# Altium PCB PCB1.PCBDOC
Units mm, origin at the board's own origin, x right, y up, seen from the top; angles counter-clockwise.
Board outline 152.4 x 101.6 mm, 2 copper layers (Top Layer, Bottom Layer); 41 components, 23 nets, 101 pads, 2 vias.
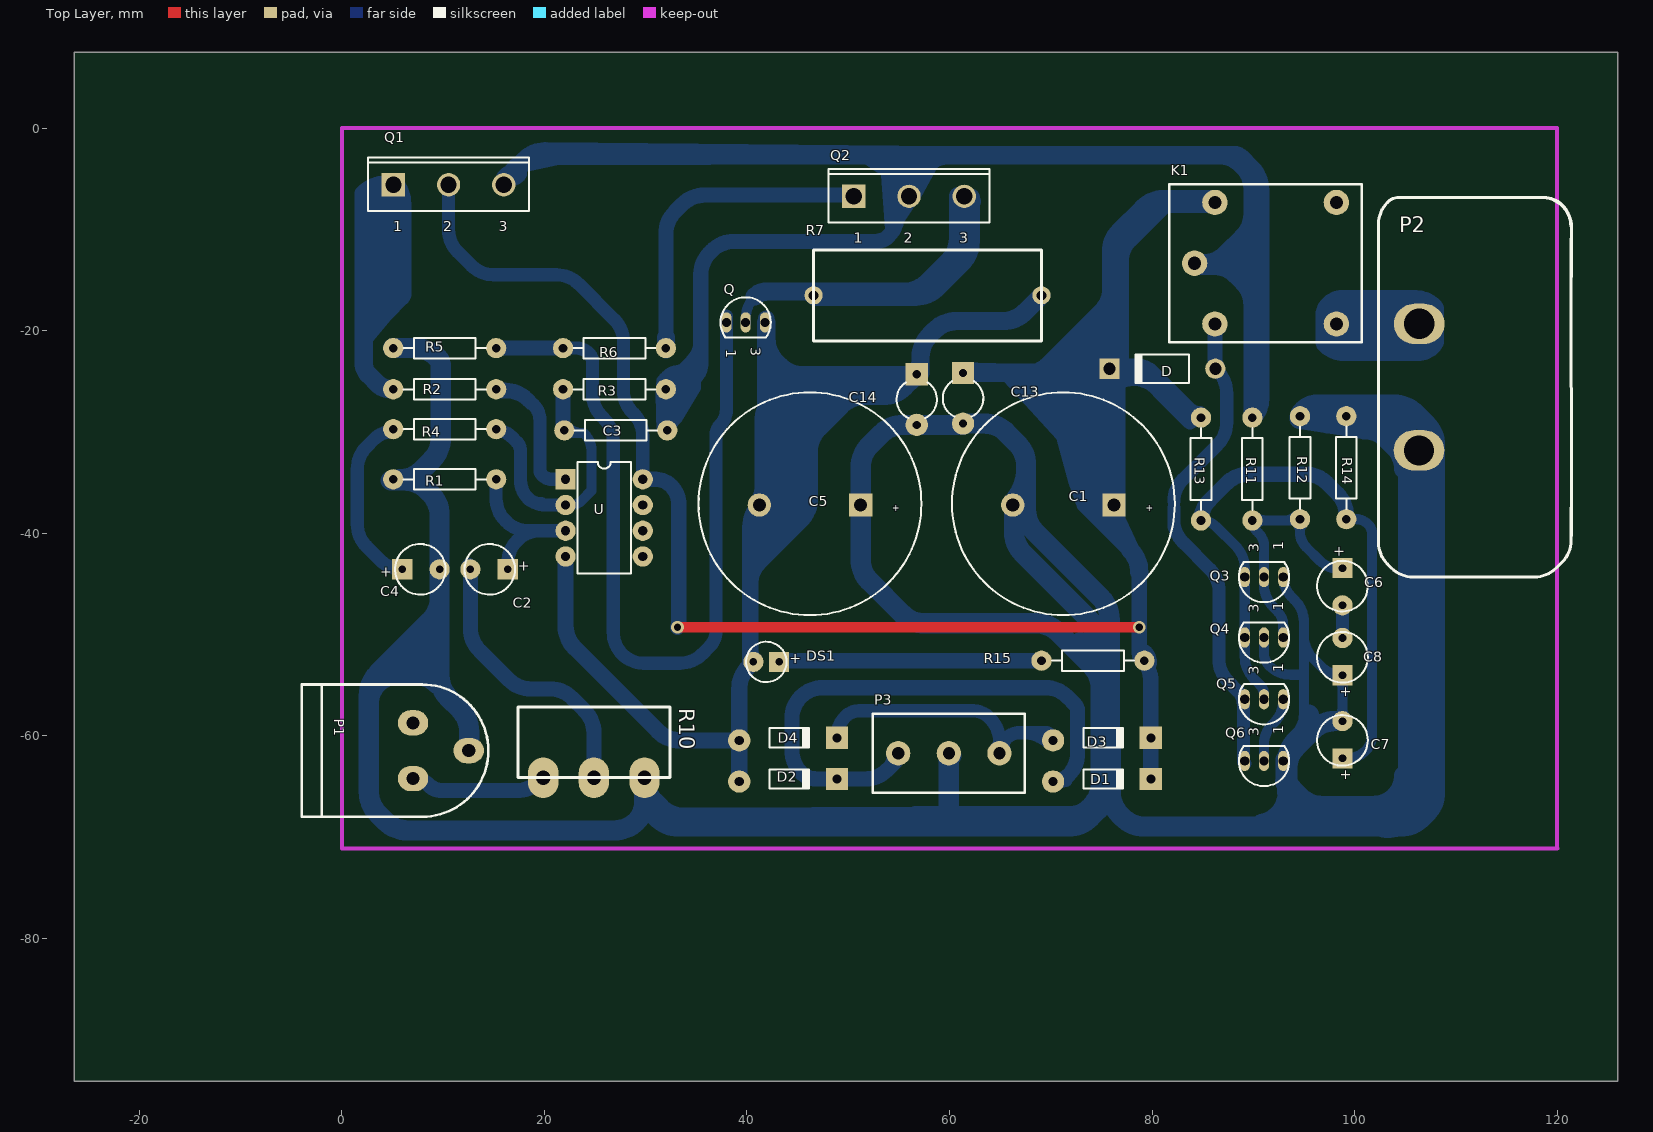
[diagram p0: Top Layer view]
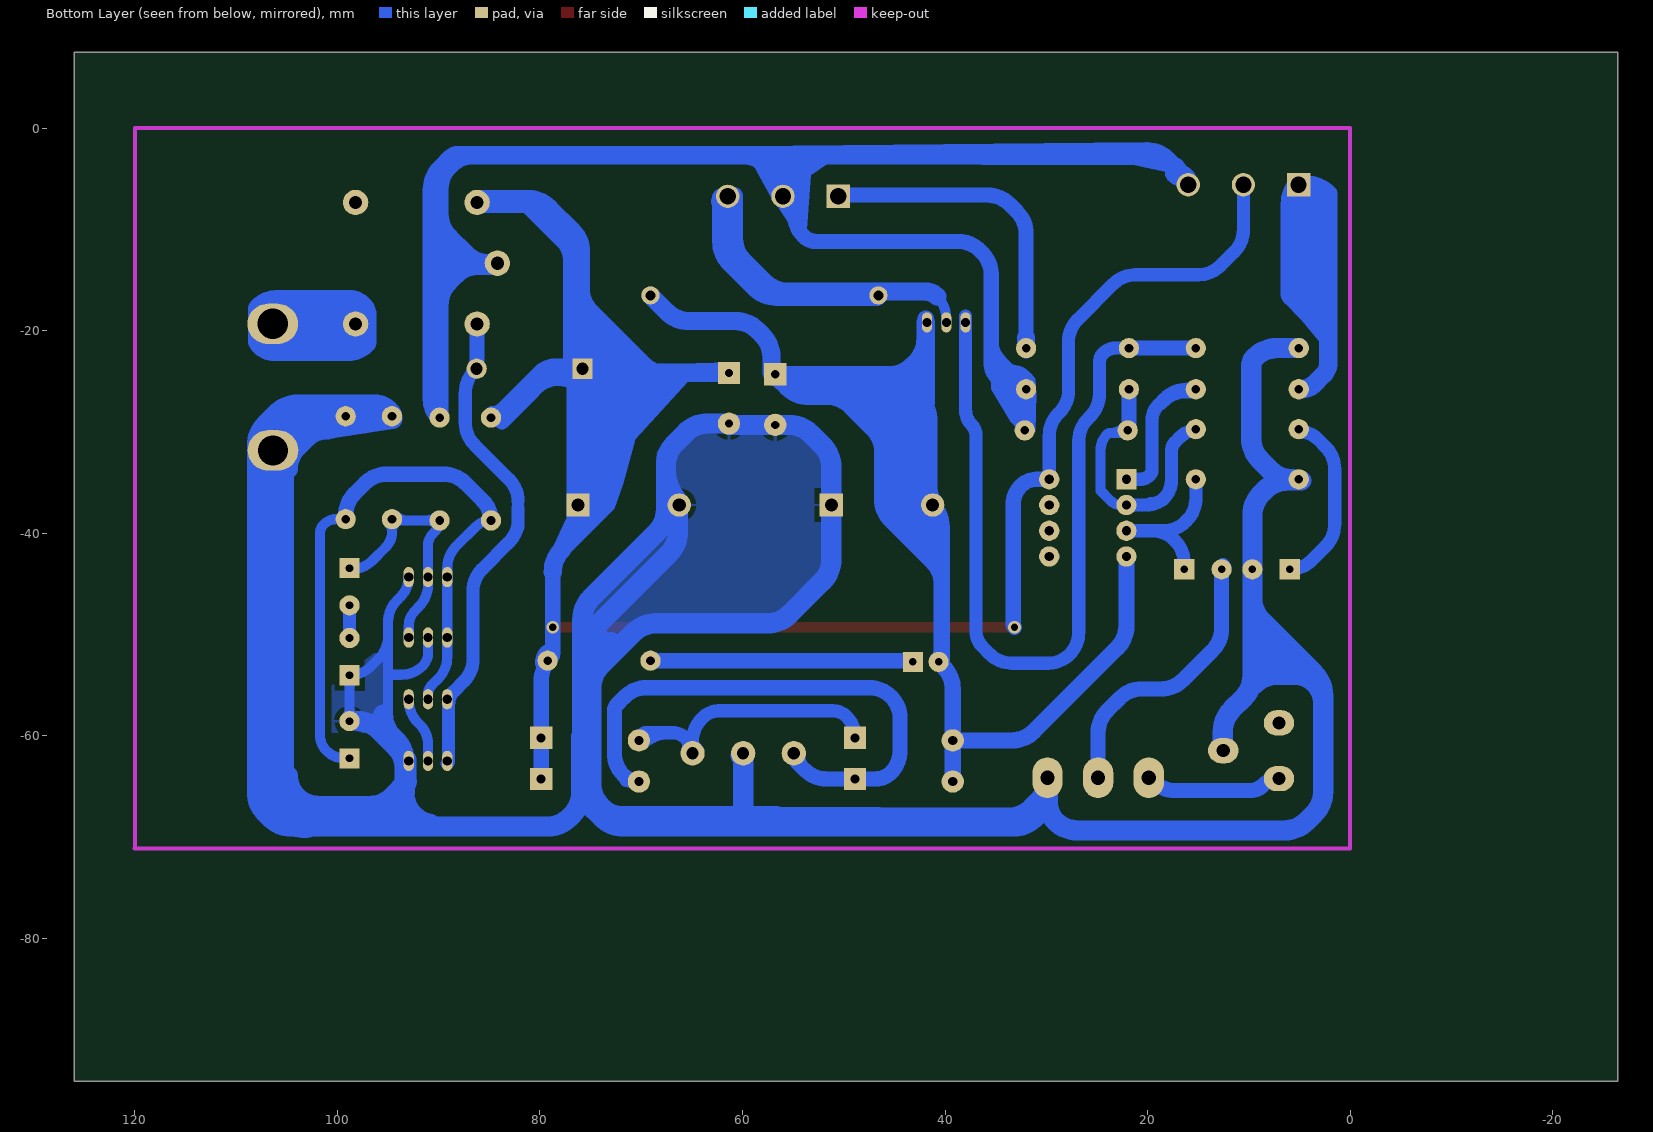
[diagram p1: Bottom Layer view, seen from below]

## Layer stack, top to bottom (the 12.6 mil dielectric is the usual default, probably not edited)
Top Layer: signal copper 0.0356
Dielectric: dielectric 0.32, FR-4, Dk 4.8
Bottom Layer: signal copper 0.0356

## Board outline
-26.416,-94.107 125.984,-94.107 125.984,7.493 -26.416,7.493

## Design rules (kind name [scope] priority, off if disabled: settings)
Clearance [All] p1: gap=0.5
ComponentClearance [All] p1: gap=0.254 collisioncheckmode=3
PolygonConnect [All] p1: connectstyle=Relief reliefconductorwidth=0.254 reliefentries=4 polygonreliefangle="90 Angle"
RoutingVias [All] p1: holewidth=0.711 width=1.27 viastyle="Through Hole" minholewidth=0.711 minwidth=1.27 maxholewidth=0.711 maxwidth=1.27
SolderMaskExpansion [All] p1: expansion=0.102
TestPointUsage [All] p1: valid=0 allowmultiple=FALSE
Testpoint [All] p1: side=3 testpointundercomponent=TRUE minsize=1.016 maxsize=2.54 preferedsize=1.524 minholesize=0 maxholesize=1.016 preferedholesize=0.813 testpointgrid=0.025 style=297 order=1234567890
Width Width_3 [InNet('GND')] p1: maxlimit=2.5 minlimit=0.8 preferedwidth=1.5 bottomlayer_prefwidth=2 minimp=50.000000 maximp=50.000000 favimp=50.000000
Width Width_2 [InNet('-12V')] p2: maxlimit=1.8 minlimit=0.5 preferedwidth=1 bottomlayer_prefwidth=1.6 minimp=50.000000 maximp=50.000000 favimp=50.000000
Width Width_1 [InNet('+12V')] p3: maxlimit=1.8 minlimit=0.5 preferedwidth=1 bottomlayer_prefwidth=1.5 minimp=50.000000 maximp=50.000000 favimp=50.000000
Width [All] p4: maxlimit=3 minlimit=0.4 preferedwidth=1 bottomlayer_prefwidth=1.5 minimp=50.000000 maximp=50.000000 favimp=50.000000
17 further rules are at their usual default settings.

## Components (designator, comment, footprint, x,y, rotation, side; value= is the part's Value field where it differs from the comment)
C1 "Cap Pol1" RB7.6-15 71.247,-37.084 r0 top
C2 "Cap Pol1" CAPPR2-5x6.8 14.605,-43.561 r180 top
C3 "Cap" AXIAL-0.4 27.051,-29.845 r0 top
C4 "Cap Pol1" CAPPR2-5x6.8 7.747,-43.561 r0 top
C5 "Cap Pol1" RB7.6-15 46.228,-37.084 r0 top
C6 "Cap Pol1" CAPPR2-5x6.8 98.806,-45.212 r270 top
C7 "Cap Pol1" CAPPR2-5x6.8 98.806,-52.248 r90 top
C8 "Cap Pol1" CAPPR2-5x6.8 98.806,-60.452 r90 top
C13 "Cap" CAPR5-4X5 61.341,-26.67 r270 top
C14 "Cap" CAPR5-4X5 56.769,-26.797 r270 top
D "1N4001" DIO10.46-5.3x2.8 81.026,-23.749 r180 top
D1 "Diode 1N914" DIO7.1-3.9x1.9 75.184,-64.262 r0 top
D2 "Diode 1N914" DIO7.1-3.9x1.9 44.196,-64.262 r0 top
D3 "Diode 1N914" DIO7.1-3.9x1.9 75.184,-60.198 r0 top
D4 "Diode 1N914" DIO7.1-3.9x1.9 44.196,-60.198 r0 top
DS1 "LED0" CAPPR1.5-4x5 41.91,-52.705 r180 top
K1 "Relay-SPDT" jidianqi 84.201,-13.335 r0 top
P1 "Header 2" 音频线 9.779,-61.468 r270 top
P2 "Header 2" pcZOU 102.362,-44.323 r90 top
P3 "Header 3" duanzi 59.944,-61.722 r180 top
Q "BC547" BCY-W3/E4 39.878,-19.177 r270 top
Q1 "IRFPC50" TO-247AC 10.541,-5.588 r0 top
Q2 "IRFPC50" TO-247AC 56.007,-6.731 r0 top
Q3 "9014" BCY-W3/E4 91.059,-44.323 r90 top
Q4 "9014" BCY-W3/E4 91.059,-50.292 r90 top
Q5 "8050" BCY-W3/E4 91.059,-56.388 r90 top
Q6 "8050" BCY-W3/E4 91.059,-62.484 r90 top
R1 "Res2" AXIAL-0.4 10.16,-34.671 r180 top
R2 "Res2" AXIAL-0.4 10.16,-25.781 r180 top
R3 "Res2" AXIAL-0.4 26.924,-25.781 r0 top
R4 "Res2" AXIAL-0.4 10.16,-29.718 r0 top
R5 "Res2" AXIAL-0.4 10.16,-21.717 r0 top
R6 "Res2" AXIAL-0.4 26.924,-21.717 r0 top
R7 "Res2" "0.02R   5W" 69.088,-16.51 r180 top
R10 "" 电位器 24.892,-64.135 r0 top
R11 "Res2" AXIAL-0.4 89.916,-33.655 r90 top
R12 "Res2" AXIAL-0.4 94.615,-33.528 r90 top
R13 "Res2" AXIAL-0.4 84.836,-33.655 r270 top
R14 "Res2" AXIAL-0.4 99.187,-33.528 r90 top
R15 "Res2" AXIAL-0.4 74.168,-52.578 r0 top
U "NE5532AP" P008 25.908,-38.481 r270 top

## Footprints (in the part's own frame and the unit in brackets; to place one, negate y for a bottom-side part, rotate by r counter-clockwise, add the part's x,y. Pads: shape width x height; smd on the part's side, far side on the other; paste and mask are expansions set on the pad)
"0.02R   5W" [mm]
  round 1.8 hole 1: 1(0,0) 2(22.5,0)
  silkscreen extent 0,-4.5 22.5,4.5
AXIAL-0.4 [mm] "Connector; Header; 2 Posi"
  round 2 hole 0.85: 1(-5.08,0) 2(5.08,0)
  silkscreen extent -4.06,-1.02 4.06,1.02
BCY-W3/E4 [mm]
  oval 2x1 hole 0.9: 1(0,-1.905) 2(0,0) 3(0,1.905)
  silkscreen extent -2.48,-2.48 1.5,2.48
CAPPR1.5-4x5 [mm]
  rect 2x2 hole 0.75: 1(-1.27,0)
  round 2 hole 0.75: 2(1.27,0)
  silkscreen extent -2,-2 2,2
CAPPR2-5x6.8 [mm] "Connector; Header; 2 Posi"
  rect 2x2 hole 0.75: 1(-1.778,0)
  round 2 hole 0.75: 2(1.905,0)
  silkscreen extent -2.5,-2.5 2.5,2.5
CAPR5-4X5 [mm] "Connector; Header; 2 Posi"
  rect 2.2x2.2 hole 0.8: 1(-2.5,0)
  round 2.2 hole 0.8: 2(2.5,0)
  silkscreen extent -1.69,-2 1.82,2
DIO7.1-3.9x1.9 [mm] "Connector; Header; 2 Posi"
  round 2.2 hole 0.9: 1(-4.953,-0.254)
  rect 2.2x2.2 hole 0.9: 2(4.699,0)
  silkscreen extent -1.95,-0.95 2.05,0.95
DIO10.46-5.3x2.8 [mm] "Connector; Header; 2 Posi"
  round 2 hole 1.2: 1(-5.23,0)
  rect 2x2 hole 1.2: 2(5.23,0)
  silkscreen extent -2.65,-1.4 2.75,1.4
duanzi [mm]
  round 2.4 hole 1.2: 1(-4.994,0) 2(0.006,0) 3(5.006,0)
  silkscreen extent -7.49,-3.9 7.51,3.9
jidianqi [mm]
  round 2.5 hole 1.3: 1(14.006,-6) 2(14.006,6) 3(0.006,0) 4(2.006,-6) 5(2.006,6)
  silkscreen extent -2.49,-7.8 16.51,7.8
P008 [mm]
  rect 2x2 hole 0.9: 1(-3.81,-3.81)
  round 2 hole 0.9: 2(-1.27,-3.81) 3(1.27,-3.81) 4(3.81,-3.81) 5(3.81,3.81) 6(1.27,3.81) 7(-1.27,3.81) 8(-3.81,3.81)
  silkscreen extent -5.5,-2.65 5.5,2.65
pcZOU [mm]
  oval 4x5 hole 3: 1(25,-4.025) 2(12.5,-4)
  silkscreen extent 0,-19.08 37.5,0
RB7.6-15 [mm]
  rect 2.3x2.3 hole 1.3: 1(5,-0.127)
  round 2.3 hole 1.3: 2(-5,-0.127)
  silkscreen extent -11,-11 11,11
TO-247AC [mm]
  rect 2.3x2.3 hole 1.6: 1(-5.45,0)
  round 2.3 hole 1.6: 2(0,0) 3(5.45,0)
  silkscreen extent -7.95,-2.6 7.95,2.7
电位器 [mm]
  oval 3x4 hole 1.4: 1(-5,0) 2(0,0) 3(5,0)
  silkscreen extent -7.51,0 7.5,6.98
音频线 [mm]
  oval 2.5x3 hole 1.3: 1(-0.007,2.75) 2(2.75,-2.75) 3(-2.75,-2.75)
  silkscreen extent -6.54,-13.75 6.52,4.69

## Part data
C1: "Polarized Capacitor (or (tor (ed Capacitor ( 2-Pin"
C2 C4: "Polarized Capacitor (tor (ed Capacitor ( 2-Pin"
C3: "CapacCapacitor (tor (ed Capacitor ( 2-Pin"
C5: "Polarized Capacitor (pacitor (ed Capacitor ( 2-Pin"
C6 C7: "Polarized Capacitor (ed Capacitor ( 2-Pin"
C8: "Polarized Capacitor ( 2-Pin"
C13 C14: "Cauctance Fasose Re=Header, 2-Pin"
D: library part "Diode 1N4001", "1 Amp General Purpose Re=Header, 2-Pin"
D1 D2 D3 D4: "High Conductance Fasose Re=Header, 2-Pin"
DS1: "Typical INFRARED G"
K1: "Single-Pole Dual-Throw"
P1 P2: "Header, 2-Pin"
P3: "HeaderFET Powere AmSOURCEDESCRIPTION=Single-Pole Dual-Throw"
Q: library part 2N3904, "NPN General Purpose AmSOURCEDESCRIPTION=Single-Pole Dual-Throw"
Q1 Q2: "HEXFET Powere AmSOURCEDESCRIPTION=Single-Pole Dual-Throw"
Q3: library part 2N3904, "NPN General Purpose AmERENCE=Relay-SPDT"
Q4 Q5 Q6: library part 2N3904, "NPN General Purpose AmGeneral Purpose AmSOURCEDESCRIPTION=Single-Pole Dual-Throw"
R1 R2 R3 R4 R5 R6: "RSOURCEDESCRIPTION=RRtional Am INFRARED G"
R7: "RRtional Am INFRARED G"
R10: library part RPot, "Potentiometer"
R11 R12 R13 R14: "RSOURCEDESCRIPTION=Rtional Am INFRARED G"
R15: "Rtional Am INFRARED G"
U: "Dual Low-Noise Operational Am INFRARED G"

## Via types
v1: diameter 1.27, hole 0.711, Top Layer to Bottom Layer, 2 vias

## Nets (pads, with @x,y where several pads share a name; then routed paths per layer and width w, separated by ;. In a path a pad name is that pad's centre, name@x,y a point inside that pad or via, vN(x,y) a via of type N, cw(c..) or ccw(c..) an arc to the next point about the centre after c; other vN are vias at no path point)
+12V: C1.1 C13.1 D1.2 D3.2 D.2 K1.5 Q1.2 R13.1 R15.2 U.8 | length 252.5
  Top Layer w1: v1(33.147,-49.276) v1(78.74,-49.276)
  Bottom Layer w1.3: Q1.2 10.541,-10.033 ccw(c13.607,-10.033) 11.439,-12.201 12.818,-13.58 ccw(c14.986,-11.412) 14.986,-14.478 21.209,-14.478 cw(c21.209,-17.544) 23.377,-15.376 26.915,-18.914 cw(c24.747,-21.082) 27.813,-21.082 27.813,-25.908 ccw(c30.879,-25.908) 28.711,-28.076 28.82,-28.185 cw(c26.652,-30.353) 29.718,-30.353 U.8
  Bottom Layer w1.5: U.8 30.979,-34.671 cw(c30.979,-36.839) 32.512,-35.306 cw(c30.672,-37.146) 33.274,-37.146 33.274,-48.969 cw(c32.84,-48.969) v1(33.147,-49.276) ; C13.1 67.524,-24.17 ccw(c67.524,-21.104) 69.692,-23.272 74.921,-18.043 ccw(c72.753,-15.875) 75.796,-16.25 ccw(c72.753,-15.875) 75.819,-15.875 ; C1.1@75.796,-36.122 75.796,-25.123 ; D.2@75.796,-23.495 78.477,-23.495 cw(c78.477,-25.663) 80.01,-24.13 83.625,-27.745 ccw(c84.709,-26.661) R13.1@84.709,-28.194 ; 75.796,-15.875 75.796,-12.215 cw(c78.862,-12.215) 76.694,-10.047 78.985,-7.756 cw(c81.153,-9.924) 81.153,-6.858 K1.5@85.725,-6.858 ; 76.581,-25.146 cw(c78.181,-27.762) 80.349,-25.594 ; 76.581,-12.192 cw(c79.34,-12.192) 77.389,-10.241 ; 76.754,-11.13 80.01,-7.874 ; 76.962,-23.876 76.962,-13.081 cw(c79.721,-13.081) 77.77,-11.13 81.026,-7.874 cw(c81.639,-8.487) 81.639,-7.62 K1.5@86.106,-7.62 ; 78.74,-43.815 78.74,-51.838 ccw(c79.607,-51.838) 78.994,-52.451 cw(c76.848,-54.597) 79.883,-54.597 D1.2 ; R15.2@79.307,-51.748 cw(c78.223,-52.832) R15.2@79.756,-52.832 ; 80.645,-25.917 83.752,-29.024 cw(c84.836,-30.108) R13.1 ; 75.796,-35.156 ccw(c78.302,-35.156) C1.1@76.53,-36.928 ; 75.796,-35.156 ccw(c78.302,-35.156) C1.1@76.53,-36.928 ; 75.796,-35.156 ccw(c78.302,-35.156) C1.1@76.53,-36.928 ; D.2@75.973,-23.926 cw(c77.013,-24.966) 77.013,-23.495 ; D.2@75.973,-23.926 cw(c77.013,-24.966) 77.013,-23.495 ; D.2@75.973,-23.926 cw(c77.013,-24.966) 77.013,-23.495 ; 78.74,-50.748 ccw(c81.078,-50.748) R15.2@79.425,-52.401 ; 78.74,-50.748 ccw(c81.078,-50.748) R15.2@79.425,-52.401 ; 78.74,-50.748 ccw(c81.078,-50.748) R15.2@79.425,-52.401 ; 83.759,-27.879 ccw(c84.836,-26.802) R13.1@84.836,-28.325 ; 83.759,-27.879 ccw(c84.836,-26.802) R13.1@84.836,-28.325 ; 83.759,-27.879 ccw(c84.836,-26.802) R13.1@84.836,-28.325 ; 83.816,-27.936 ccw(c84.76,-26.991) R13.1@84.824,-28.325 ; 83.816,-27.936 ccw(c84.76,-26.991) R13.1@84.824,-28.325 ; 83.816,-27.936 ccw(c84.76,-26.991) R13.1@84.824,-28.325 ; 83.849,-6.858 cw(c83.849,-9.694) K1.5@85.854,-7.689 ; 83.849,-6.858 cw(c83.849,-9.694) K1.5@85.854,-7.689 ; 83.849,-6.858 cw(c83.849,-9.694) K1.5@85.854,-7.689
  Bottom Layer w1.8: 77.842,-41.647 cw(c75.674,-43.815) 78.74,-43.815
-12V: C5.2 C14.1 D2.1 D4.1 DS1.2 Q.3 R7.1 U.4 | length 187.1
  Bottom Layer w1.3: Q.3@41.783,-19.852 Q.3 ; C14.1 C14.1@57.277,-24.297
  Bottom Layer w1.6: U.4 22.098,-49.149 ccw(c25.164,-49.149) 22.996,-51.317 31.233,-59.554 ccw(c33.401,-57.386) 33.401,-60.452 D4.1 ; D2.1@39.116,-64.643 ccw(c38.809,-64.336) 39.243,-64.336 39.243,-55.372 cw(c42.309,-55.372) 40.141,-53.204 40.33,-53.015 40.33,-39.379 cw(c43.396,-39.379) C5.2 ccw(c40.501,-36.484) 41.402,-36.979 ccw(c40.501,-36.484) 41.529,-36.484 41.529,-28.956 cw(c44.595,-28.956) 42.427,-26.788 44.02,-25.195 cw(c46.188,-27.363) 46.188,-24.297 ; 40.33,-45.014 cw(c43.396,-45.014) 41.228,-42.846 45.33,-38.744 ccw(c43.162,-36.576) 46.228,-36.576 46.228,-31.877 cw(c49.294,-31.877) 47.126,-29.709 49.394,-27.441 cw(c51.562,-29.609) 51.562,-26.543 53.467,-26.543 ccw(c53.467,-23.477) 55.635,-25.645 56.462,-24.818 cw(c56.896,-25.251) C14.1@56.896,-24.638 ; C5.2@41.647,-37.347 ccw(c39.479,-35.179) 42.545,-35.179 42.545,-29.591 cw(c45.611,-29.591) 43.443,-27.423 45.33,-25.536 cw(c47.498,-27.704) 47.498,-24.638 C14.1@56.769,-24.638 ; 41.783,-27.095 Q.3 ; Q.3@42.037,-19.177 42.037,-20.828 ccw(c45.103,-20.828) 42.049,-21.102 ccw(c45.103,-20.828) 42.935,-22.996 43.338,-23.399 ccw(c45.506,-21.231) 45.506,-24.297 C14.1 ; 40.33,-51.474 ccw(c41.871,-51.474) DS1.2@40.781,-52.564 ; 40.33,-51.474 ccw(c41.871,-51.474) DS1.2@40.781,-52.564 ; 40.33,-51.474 ccw(c41.871,-51.474) DS1.2@40.781,-52.564 ; C5.2@40.981,-36.964 ccw(c39.656,-35.639) 41.529,-35.639 ; C5.2@40.981,-36.964 ccw(c39.656,-35.639) 41.529,-35.639 ; C5.2@40.981,-36.964 ccw(c39.656,-35.639) 41.529,-35.639 ; 55.221,-24.638 ccw(c55.221,-22.749) C14.1@56.557,-24.085 ; 55.221,-24.638 ccw(c55.221,-22.749) C14.1@56.557,-24.085 ; 55.221,-24.638 ccw(c55.221,-22.749) C14.1@56.557,-24.085
  Bottom Layer w1.8: C14.1@57.15,-24.17 57.15,-22.606 cw(c60.216,-22.606) 58.048,-20.438 58.538,-19.948 cw(c60.706,-22.116) 60.706,-19.05 65.278,-19.05 ccw(c65.278,-15.984) 67.446,-18.152 R7.1 ; C14.1@56.628,-24.156 ccw(c55.366,-22.894) 57.15,-22.894 ; C14.1@56.628,-24.156 ccw(c55.366,-22.894) 57.15,-22.894 ; C14.1@56.628,-24.156 ccw(c55.366,-22.894) 57.15,-22.894
GND: C1.2 C4.2 C5.1 C7.1 C8.2 C13.2 C14.2 P1.1 P2.2 P3.2 Q3.1 Q4.2 Q6.1 R1.2 R5.1 R10.3 R12.2 R14.2 | length 730.3
  Bottom Layer w1: Q4.2 91.059,-51.86 ccw(c92.793,-51.86) 91.567,-53.086 ccw(c93.713,-50.94) 93.713,-53.975 94.996,-53.975 ; Q3.1 ccw(c95.723,-44.323) 93.772,-46.274 94.098,-46.6 cw(c91.93,-48.768) 94.996,-48.768 94.996,-58.494 ccw(c95.43,-58.494) 95.123,-58.801 ; 94.996,-50.165 ccw(c98.062,-50.165) 95.894,-52.333 96.725,-53.164 ccw(c98.806,-51.082) C7.1@98.261,-53.975 ; C8.2@98.044,-58.547 C8.2 ; C7.1@98.683,-53.975 cw(c98.683,-54.148) C7.1 C8.2@98.806,-57.934 ; C4.2@9.298,-43.915 cw(c8.445,-44.768) 9.652,-44.768 ; C4.2@9.298,-43.915 cw(c8.445,-44.768) 9.652,-44.768 ; C4.2@9.298,-43.915 cw(c8.445,-44.768) 9.652,-44.768 ; 9.652,-44.768 cw(c10.859,-44.768) C4.2@10.006,-43.915 ; 9.652,-44.768 cw(c10.859,-44.768) C4.2@10.006,-43.915 ; 9.652,-44.768 cw(c10.859,-44.768) C4.2@10.006,-43.915 ; R12.2@94.969,-28.802 cw(c95.822,-29.655) 95.822,-28.448 ; R12.2@94.969,-28.802 cw(c95.822,-29.655) 95.822,-28.448 ; R12.2@94.969,-28.802 cw(c95.822,-29.655) 95.822,-28.448 ; R12.2@94.969,-28.094 ccw(c95.822,-27.241) 95.822,-28.448 ; R12.2@94.969,-28.094 ccw(c96.129,-26.934) 96.129,-28.575 ; R12.2@94.969,-28.094 ccw(c95.822,-27.241) 95.822,-28.448 ; R12.2@94.969,-28.094 ccw(c96.129,-26.934) 96.129,-28.575 ; R12.2@94.969,-28.094 ccw(c95.822,-27.241) 95.822,-28.448 ; R12.2@94.969,-28.094 ccw(c96.129,-26.934) 96.129,-28.575 ; 97.673,-28.575 ccw(c97.673,-26.934) R14.2@98.833,-28.094 ; 97.673,-28.575 ccw(c97.673,-26.934) R14.2@98.833,-28.094 ; 97.673,-28.575 ccw(c97.673,-26.934) R14.2@98.833,-28.094 ; 97.98,-28.448 cw(c97.98,-29.655) R14.2@98.833,-28.802 ; 97.98,-28.448 ccw(c97.98,-27.241) R14.2@98.833,-28.094 ; 97.98,-28.448 cw(c97.98,-29.655) R14.2@98.833,-28.802 ; 97.98,-28.448 ccw(c97.98,-27.241) R14.2@98.833,-28.094 ; 97.98,-28.448 cw(c97.98,-29.655) R14.2@98.833,-28.802 ; 97.98,-28.448 ccw(c97.98,-27.241) R14.2@98.833,-28.094 ; C8.2@98.452,-58.193 ccw(c97.599,-57.34) 98.806,-57.34 ; C8.2@98.452,-58.193 ccw(c97.599,-57.34) 98.806,-57.34 ; C8.2@98.452,-58.193 ccw(c97.599,-57.34) 98.806,-57.34 ; C7.1@98.452,-54.379 cw(c97.599,-55.233) 98.806,-55.233 ; C7.1@98.452,-54.379 cw(c97.599,-55.233) 98.806,-55.233 ; C7.1@98.452,-54.379 cw(c97.599,-55.233) 98.806,-55.233 ; 98.806,-57.34 ccw(c100.013,-57.34) C8.2@99.16,-58.193 ; 98.806,-57.34 ccw(c100.013,-57.34) C8.2@99.16,-58.193 ; 98.806,-57.34 ccw(c100.013,-57.34) C8.2@99.16,-58.193 ; 98.806,-55.233 cw(c100.013,-55.233) C7.1@99.16,-54.379 ; 98.806,-55.233 cw(c100.013,-55.233) C7.1@99.16,-54.379 ; 98.806,-55.233 cw(c100.013,-55.233) C7.1@99.16,-54.379 ; R12.2 ccw(c94.922,-28.141) 94.922,-28.575 99.314,-28.575 ccw(c99.007,-28.882) 99.007,-28.448 R12.2
  Bottom Layer w1.5: R14.2 101.981,-28.448 cw(c101.981,-31.514) 104.149,-29.346 P2.2@106.553,-31.75 ; 104.529,-28.329 cw(c102.357,-30.501) P2.2@105.39,-30.989 ; 103.767,-28.964 cw(c101.595,-31.136) P2.2@104.628,-31.624 ; 103.767,-28.964 cw(c101.595,-31.136) P2.2@104.628,-31.624 ; 103.767,-28.964 cw(c101.595,-31.136) P2.2@104.628,-31.624
  Bottom Layer w2: 2.667,-56.769 cw(c5.426,-56.769) 3.475,-54.818 cw(c5.51,-56.852) 5.51,-53.975 7.239,-53.975 cw(c7.239,-57.041) 9.407,-54.873 ; R1.2@4.826,-34.798 6.223,-34.798 cw(c6.223,-37.864) 7.798,-35.233 cw(c6.223,-37.864) 8.391,-35.696 8.754,-36.059 cw(c6.586,-38.227) 9.652,-38.227 9.652,-54.102 ccw(c12.718,-54.102) 10.55,-56.27 11.675,-57.395 cw(c9.507,-59.563) 12.573,-59.563 P1.1@12.573,-61.087 ; R5.1 7.239,-21.717 cw(c7.239,-24.783) 9.407,-22.615 cw(c8.509,-23.513) 9.779,-23.513 9.779,-30.607 cw(c6.713,-30.607) 8.881,-32.775 7.883,-33.773 cw(c5.715,-31.605) R1.2@5.715,-34.671 ; 5.461,-53.213 ccw(c5.461,-51.987) 6.328,-52.854 ; 5.588,-52.705 ccw(c5.588,-50.559) 7.106,-52.076 8.075,-51.107 cw(c8.509,-51.54) 8.509,-50.927 ; 6.604,-52.578 7.97,-52.578 cw(c7.97,-53.879) 8.89,-52.959 ; 9.652,-46.482 cw(c6.586,-46.482) 8.754,-48.65 3.565,-53.839 ccw(c5.733,-56.007) 2.667,-56.007 2.667,-65.532 ccw(c5.733,-65.532) 2.933,-66.78 ccw(c5.733,-65.532) 3.565,-67.7 4.309,-68.444 ccw(c6.477,-66.276) 6.477,-69.342 26.924,-69.342 ccw(c26.924,-66.276) 29.092,-68.444 ccw(c27.274,-66.626) 29.845,-66.656 ccw(c27.274,-66.626) 29.845,-66.626 R10.3@29.845,-63.754 ; R10.3 29.892,-64.309 ccw(c32.958,-64.309) 30.79,-66.477 31.487,-67.174 ccw(c33.655,-65.006) 33.655,-68.072 71.882,-67.945 ; R10.3@29.972,-64.389 29.972,-65.659 ccw(c33.038,-65.659) 30.87,-67.827 31.106,-68.063 ccw(c33.274,-65.895) 33.274,-68.961 71.755,-68.961 ccw(c71.755,-65.895) 73.923,-68.063 74.667,-67.319 ccw(c72.499,-65.151) 75.565,-65.151 ; 56.642,-67.945 ccw(c56.821,-64.884) 56.999,-67.945 71.882,-67.945 ; P3.2 59.938,-67.316 ccw(c60.827,-67.316) 60.198,-67.945 ; C13.2@61.341,-29.297 55.412,-29.297 ccw(c55.412,-32.363) 54.826,-29.354 ccw(c55.412,-32.363) 53.244,-30.195 52.126,-31.313 ccw(c54.294,-33.481) 51.228,-33.481 51.228,-42.592 ccw(c54.294,-42.592) 52.126,-44.76 55.363,-47.997 ccw(c57.531,-45.829) 57.531,-48.895 68.58,-48.895 cw(c68.58,-51.961) 70.748,-49.793 74.032,-53.077 cw(c71.864,-55.245) 74.93,-55.245 74.93,-64.77 cw(c71.864,-64.77) 74.032,-66.938 ; C13.2 63.46,-29.17 cw(c63.46,-32.236) 64.703,-29.433 cw(c63.46,-32.236) 65.628,-30.068 66.666,-31.106 cw(c64.498,-33.274) 67.564,-33.274 67.564,-37.719 ccw(c70.63,-37.719) 68.462,-39.887 74.921,-46.346 cw(c72.753,-48.514) 75.819,-48.514 75.819,-59.764 ccw(c76.253,-59.764) 75.946,-60.071 75.946,-65.659 ccw(c79.012,-65.659) 76.844,-67.827 77.08,-68.063 ccw(c79.248,-65.895) 79.248,-68.961 102.531,-68.961 ccw(c103.381,-66.015) 106.427,-65.671 106.43,-64.867 P2.2@106.553,-31.824 ; C1.2@66.374,-37.211 66.374,-39.831 ccw(c69.44,-39.831) 67.272,-41.999 75.048,-49.775 cw(c72.88,-51.943) 75.819,-51.07 ; 73.152,-51.562 ccw(c72.232,-51.562) 73.107,-51.277 ccw(c72.232,-51.562) 73.079,-51.203 cw(c75.964,-50.165) 72.949,-50.724 75.048,-52.823 cw(c72.88,-54.991) 75.819,-54.118 ; 73.833,-67.137 cw(c71.882,-65.186) 71.882,-67.945 ; 90.805,-68.707 ccw(c90.314,-65.681) 93.151,-64.52 ; 93.218,-64.643 Q6.1@93.218,-62.357 ; 93.345,-65.278 ccw(c96.411,-65.278) 94.243,-67.446 ; Q6.1@93.345,-63.246 cw(c96.411,-63.246) 94.243,-61.078 95.876,-59.445 cw(c98.044,-61.613) C8.2@98.044,-58.547 ; 93.726,-65.786 cw(c93.726,-67.012) 94.593,-66.145 95.114,-66.666 ccw(c97.282,-64.498) 97.282,-67.564 102.743,-67.564 ccw(c102.743,-64.498) 104.911,-66.666 ; 95.504,-57.912 cw(c92.438,-57.912) 94.606,-60.08 94.243,-60.443 ccw(c96.411,-62.611) 93.345,-62.611 93.345,-64.262 cw(c90.279,-64.262) 93.339,-64.454 ccw(c96.157,-63.246) 93.989,-65.414 94.606,-66.031 ccw(c96.774,-63.863) 96.774,-66.929 101.854,-66.929 ccw(c101.854,-63.863) 104.022,-66.031 ccw(c101.898,-63.907) 104.902,-63.907 ; 104.521,-68.961 ccw(c104.521,-65.895) 106.689,-68.063 107.052,-67.7 ccw(c104.884,-65.532) 107.95,-65.532 107.95,-31.369 ccw(c104.884,-31.369) 107.052,-29.201 106.054,-28.203 ccw(c103.886,-30.371) 103.886,-27.305 96.341,-27.305 ccw(c96.341,-29.326) 94.912,-27.897 ccw(c95.73,-28.715) 94.573,-28.715 99.035,-29.415 100.965,-29.718 cw(c100.965,-32.784) 103.133,-30.616 104.004,-31.487 cw(c101.836,-33.655) 104.902,-33.655 ; 105.283,-64.008 105.283,-33.756 ; C1.2@66.141,-37.105 ccw(c62.705,-33.669) 67.564,-33.669 ; C1.2@66.141,-37.105 ccw(c62.705,-33.669) 67.564,-33.669 ; C1.2@66.141,-37.105 ccw(c62.705,-33.669) 67.564,-33.669 ; 97.331,-29.148 ccw(c97.642,-27.163) R14.2 ; 97.331,-29.148 ccw(c97.642,-27.163) R14.2 ; 97.331,-29.148 ccw(c97.642,-27.163) R14.2 ; R14.2 ccw(c101.145,-27.577) 100.813,-29.694 ; R14.2 ccw(c101.145,-27.577) 100.813,-29.694 ; R14.2 ccw(c101.145,-27.577) 100.813,-29.694 ; 105.283,-35.635 cw(c109.674,-35.635) P2.2@106.569,-32.53 ; 105.283,-35.635 cw(c109.674,-35.635) P2.2@106.569,-32.53 ; 105.283,-35.635 cw(c109.674,-35.635) P2.2@106.569,-32.53 ; 105.283,-33.841 cw(c106.362,-33.841) P2.2@106.103,-32.794 ; 105.283,-33.841 cw(c106.362,-33.841) P2.2@106.103,-32.794 ; 105.283,-33.841 cw(c106.362,-33.841) P2.2@106.103,-32.794 ; P2.2@105.652,-32.527 cw(c103.476,-34.688) 106.542,-34.699 ; P2.2@105.652,-32.527 cw(c103.476,-34.688) 106.542,-34.699 ; P2.2@105.652,-32.527 cw(c103.476,-34.688) 106.542,-34.699
NetC2_1: C2.1 R1.1 U.3 | length 16.4
  Bottom Layer w1.3: R1.1 15.24,-36.576 ccw(c18.306,-36.576) 16.138,-38.744 16.247,-38.853 ccw(c18.415,-36.685) 18.415,-39.751 U.3 ; C2.1 16.383,-42.926 cw(c19.449,-42.926) 17.281,-40.758 17.39,-40.649 cw(c19.558,-42.817) 19.558,-39.751
  Bottom Layer w1.5: R1.1@15.367,-34.925 R1.1@15.367,-34.671
NetC2_2: C2.2 R10.2 | length 28.4
  Bottom Layer w1.5: C2.2@12.446,-43.561 12.446,-43.434 12.483,-43.397 ccw(c12.266,-43.18) C2.2@12.573,-43.18 ; C2.2 12.7,-49.403 ccw(c15.766,-49.403) 13.598,-51.571 16.501,-54.474 ccw(c18.669,-52.306) 18.669,-55.372 20.574,-55.372 cw(c20.574,-58.438) 22.742,-56.27 23.994,-57.522 cw(c21.826,-59.69) 24.892,-59.69 R10.2 ; R10.2@25.019,-64.389 R10.2@25.019,-64.135
NetC3_1: C3.1 R3.1 R4.2 U.2 | length 33
  Bottom Layer w1: C3.1@21.717,-30.099 23.696,-30.099 ; U.2 22.606,-37.211 ccw(c22.606,-35.678) 23.199,-37.092 ccw(c22.606,-35.678) 23.69,-36.762 24.638,-35.814 24.638,-31.759 ccw(c22.47,-31.759) 24.003,-30.226 ccw(c23.696,-30.533) 23.923,-30.163 ccw(c23.696,-30.533) 23.696,-30.099 ; C3.1@22.338,-29.505 ccw(c23.696,-28.248) 23.696,-30.099 ; C3.1@22.338,-29.505 ccw(c23.696,-28.248) 23.696,-30.099 ; C3.1@22.338,-29.505 ccw(c23.696,-28.248) 23.696,-30.099
  Bottom Layer w1.3: R4.2@15.24,-29.845 cw(c15.24,-31.991) 16.758,-30.474 17.272,-30.988 cw(c16.352,-31.908) 17.653,-31.908 17.653,-34.78 ccw(c20.149,-34.78) 18.384,-36.545 ccw(c19.685,-35.244) 19.138,-37.001 ; 19.685,-37.084 cw(c19.685,-35.244) 19.138,-37.001 ; R3.1@21.844,-26.035 R3.1 ; U.2 20.062,-37.211 cw(c20.062,-35.074) 19.138,-37.001
  Bottom Layer w1.5: C3.1@21.844,-29.845 R3.1@21.844,-25.527
NetC4_1: C4.1 R4.1 | length 17.7
  Bottom Layer w1.3: R4.1@4.953,-29.972 ccw(c4.953,-32.425) 3.219,-30.69 2.422,-31.487 ccw(c4.59,-33.655) 1.524,-33.655 1.524,-39.116 ccw(c4.59,-39.116) 2.422,-41.284 3.801,-42.663 ccw(c5.969,-40.495) C4.1
NetC6_1: C6.1 Q3.2 Q4.1 R11.1 R12.1 | length 39.6
  Bottom Layer w1: Q4.1 92.964,-49.158 ccw(c90.796,-49.158) 92.329,-47.625 91.957,-47.253 cw(c94.125,-45.085) 91.059,-45.085 91.059,-41.231 ccw(c89.325,-41.231) 90.551,-40.005 90.365,-39.819 cw(c91.449,-38.735) R11.1 94.308,-38.735 ccw(c94.308,-38.301) R12.1 94.615,-39.869 ccw(c96.783,-39.869) 95.25,-41.402 96.511,-42.663 ccw(c98.679,-40.495) C6.1@98.679,-43.561 ; R11.1@90.27,-39.089 cw(c91.123,-39.942) 91.123,-38.735 ; R11.1@90.27,-39.089 cw(c91.123,-39.942) 91.123,-38.735 ; R11.1@90.27,-39.089 cw(c91.123,-39.942) 91.123,-38.735 ; R11.1@90.27,-38.381 ccw(c91.123,-37.528) 91.123,-38.735 ; R11.1@90.27,-38.381 ccw(c91.123,-37.528) 91.123,-38.735 ; R11.1@90.27,-38.381 ccw(c91.123,-37.528) 91.123,-38.735 ; 93.101,-38.735 ccw(c93.101,-37.094) R12.1@94.261,-38.254 ; 93.101,-38.735 ccw(c93.101,-37.094) R12.1@94.261,-38.254 ; 93.101,-38.735 ccw(c93.101,-37.094) R12.1@94.261,-38.254 ; R12.1@94.261,-38.962 cw(c93.408,-39.815) 94.615,-39.815 ; R12.1@94.261,-38.962 cw(c93.408,-39.815) 94.615,-39.815 ; R12.1@94.261,-38.962 cw(c93.408,-39.815) 94.615,-39.815 ; 94.615,-39.815 cw(c95.822,-39.815) R12.1@94.969,-38.962 ; 94.615,-39.815 cw(c95.822,-39.815) R12.1@94.969,-38.962 ; 94.615,-39.815 cw(c95.822,-39.815) R12.1@94.969,-38.962
NetC6_2: C6.2 C7.2 | length 3.8
  Bottom Layer w0.8: C7.2@98.806,-50.038 C7.2@99.187,-50.419
  Bottom Layer w1.3: C7.2 C6.2
NetC8_1: C8.1 Q3.3 Q4.3 Q5.2 R13.2 R14.1 | length 71.8
  Bottom Layer w1: R13.2 cw(c84.836,-40.881) 86.354,-39.364 88.256,-41.266 cw(c86.088,-43.434) 89.127,-43.026 cw(c86.088,-43.434) 89.154,-43.434 Q3.3@89.154,-44.577 ; Q3.3@89.154,-44.862 89.154,-52.197 ccw(c92.22,-52.197) 90.052,-54.365 90.678,-54.991 cw(c89.758,-55.911) 91.059,-55.911 Q5.2 ; C8.1 99.252,-62.23 ccw(c99.252,-59.628) 99.905,-62.147 ccw(c99.252,-59.628) 101.092,-61.468 ccw(c99.559,-59.935) 101.683,-60.369 ccw(c99.559,-59.935) 101.727,-59.935 101.727,-40.036 ccw(c100.426,-40.036) 101.716,-39.867 ccw(c100.426,-40.036) 101.346,-39.116 ccw(c100.12,-40.342) 100.499,-38.65 ccw(c100.12,-40.342) R14.1@100.12,-38.608 ; R14.1@99.097,-38.01 cw(c98.88,-38.227) 99.165,-38.112 cw(c98.88,-38.227) R14.1@99.187,-38.227 ; 90.694,-55.007 cw(c89.813,-55.888) Q5.2@91.059,-55.888 ; 90.694,-55.007 cw(c89.813,-55.888) Q5.2@91.059,-55.888 ; 90.694,-55.007 cw(c89.813,-55.888) Q5.2@91.059,-55.888 ; 90.694,-55.007 cw(c89.813,-55.888) Q5.2@91.059,-55.888 ; 90.694,-55.007 cw(c89.813,-55.888) Q5.2@91.059,-55.888 ; 90.694,-55.007 cw(c89.813,-55.888) Q5.2@91.059,-55.888
  Bottom Layer w1.5: R13.2 cw(c87.595,-38.735) 85.644,-36.784 87.367,-35.061 cw(c89.535,-37.229) 89.535,-34.163 95.123,-34.163 cw(c95.123,-37.229) 97.291,-35.061 98.289,-36.059 cw(c96.121,-38.227) 99.187,-38.227 R14.1
NetD1_1: D1.1 D2.2 P3.3 | length 61.2
  Bottom Layer w1.3: D1.1 70.612,-64.516 ccw(c70.612,-61.45) 71.508,-64.382
  Bottom Layer w1.5: D1.1 ccw(c70.231,-62.37) 71.749,-63.887 ccw(c69.587,-61.726) 72.644,-61.726 72.644,-57.509 ccw(c71.777,-57.509) 72.39,-56.896 71.637,-56.143 ccw(c69.469,-58.311) 69.469,-55.245 47.498,-55.245 ccw(c47.498,-58.311) 45.33,-56.143 ccw(c47.454,-58.267) 44.45,-58.267 44.45,-61.468 ccw(c47.516,-61.468) 44.738,-62.766 ccw(c47.516,-61.468) 45.348,-63.636 ccw(c46.859,-62.125) 46.138,-64.137 ccw(c46.859,-62.125) 46.859,-64.262 51.689,-64.262 ccw(c51.689,-61.196) 52.585,-64.128 ccw(c51.689,-61.196) 53.857,-63.364 54.541,-62.68 ccw(c53.582,-61.722) P3.3@54.937,-61.776 ; 54.138,-63.083 ccw(c53.182,-62.127) P3.3@54.499,-61.823 ; 54.138,-63.083 ccw(c53.182,-62.127) P3.3@54.499,-61.823 ; 54.138,-63.083 ccw(c53.182,-62.127) P3.3@54.499,-61.823 ; P3.3@54.937,-61.776 ccw(c53.582,-61.722) P3.3 54.938,-61.775 P3.3@54.937,-61.776
NetD3_1: D3.1 D4.2 P3.1 | length 45.9
  Bottom Layer w1.3: D4.2 48.895,-60.113 cw(c51.756,-60.113) 49.155,-58.922 cw(c51.756,-60.113) 49.733,-58.09 cw(c51.082,-59.439) 50.131,-57.785 cw(c51.082,-59.439) 51.082,-57.531 62.348,-57.531 cw(c62.348,-59.699) 63.366,-57.785 cw(c62.348,-59.699) 63.381,-57.793 cw(c62.348,-59.699) 63.881,-58.166 64.04,-58.325 cw(c61.872,-60.493) 64.497,-58.909 cw(c61.872,-60.493) 64.938,-60.493 ; P3.1 64.938,-60.493 ; P3.1@64.938,-61.595 cw(c65.649,-61.595) P3.1@65.146,-61.092 ; P3.1@64.938,-61.221 cw(c65.666,-61.221) 65.151,-60.706 65.628,-60.229 ; D3.1 ccw(c69.618,-60.452) 70.051,-60.018 69.85,-59.817 ccw(c69.543,-60.124) 69.543,-59.69 66.929,-59.69 ccw(c66.929,-61.53) 65.628,-60.229 ; P3.1@64.571,-61.312 ccw(c63.839,-60.493) 64.938,-60.493 ; P3.1@64.571,-61.312 ccw(c63.839,-60.493) 64.938,-60.493 ; P3.1@64.571,-61.312 ccw(c63.839,-60.493) 64.938,-60.493 ; 64.938,-60.493 ccw(c66.036,-60.493) P3.1@65.304,-61.312 ; 64.938,-60.493 ccw(c66.036,-60.493) P3.1@65.304,-61.312 ; 64.938,-60.493 ccw(c66.036,-60.493) P3.1@65.304,-61.312 ; P3.1@65.429,-61.474 cw(c66.389,-60.989) 65.628,-60.229 ; P3.1@65.429,-61.474 cw(c66.389,-60.989) 65.628,-60.229 ; P3.1@65.429,-61.474 cw(c66.389,-60.989) 65.628,-60.229 ; 67.305,-59.69 cw(c67.305,-63.378) D3.1@69.913,-60.77 ; 67.305,-59.69 cw(c67.305,-63.378) D3.1@69.913,-60.77 ; 67.305,-59.69 cw(c67.305,-63.378) D3.1@69.913,-60.77
NetD_1: D.1 K1.4 Q5.3 Q6.3 | length 60.6
  Bottom Layer w1.3: 82.169,-39.37 82.169,-37.465 ; 82.169,-38.735 ccw(c85.235,-38.735) 83.067,-40.903 85.716,-43.552 cw(c83.548,-45.72) 86.614,-45.72 86.614,-52.451 ccw(c89.68,-52.451) 87.512,-54.619 88.488,-55.595 cw(c87.187,-56.896) 89.027,-56.896 89.027,-62.431 ccw(c89.461,-62.431) Q6.3@89.154,-62.738 ; 82.169,-36.83 cw(c85.235,-36.83) 83.067,-34.662 86.478,-31.251 ccw(c84.31,-29.083) 87.376,-29.083 87.376,-26.139 ccw(c84.31,-26.139) 86.478,-23.971 D.1 ; K1.4@86.106,-19.05 86.106,-23.517 ccw(c86.973,-23.517) D.1@86.36,-24.13 ; 86.106,-22.542 ccw(c87.463,-22.542) D.1@86.504,-23.502 ; 86.106,-22.542 ccw(c87.463,-22.542) D.1@86.504,-23.502 ; 86.106,-22.542 ccw(c87.463,-22.542) D.1@86.504,-23.502 ; 86.106,-21.028 cw(c87.901,-21.028) K1.4@86.632,-19.759 ; 86.106,-21.028 cw(c87.901,-21.028) K1.4@86.632,-19.759 ; 86.106,-21.028 cw(c87.901,-21.028) K1.4@86.632,-19.759
  Bottom Layer w1.5: K1.4 86.207,-23.632 ccw(c86.373,-23.632) D.1
NetDS1_1: DS1.1 R15.1 | length 25.7
  Bottom Layer w1.5: DS1.1@43.434,-52.578 R15.1
NetK1_1: K1.1 P2.1 | length 67.8
  Bottom Layer w1.3: K1.1 K1.1@98.552,-19.335 ; P2.1@106.732,-19.335 ccw(c106.732,-19.229) P2.1@106.807,-19.304 ; K1.1@98.632,-19.759 cw(c99.656,-20.784) 99.656,-19.335 ; K1.1@98.632,-19.759 cw(c99.656,-20.784) 99.656,-19.335 ; K1.1@98.632,-19.759 cw(c99.656,-20.784) 99.656,-19.335 ; K1.1@98.632,-18.911 ccw(c99.656,-17.886) 99.656,-19.335 ; K1.1@98.632,-18.911 ccw(c99.656,-17.886) 99.656,-19.335 ; K1.1@98.632,-18.911 ccw(c99.656,-17.886) 99.656,-19.335 ; 102.599,-19.335 ccw(c102.599,-16.035) P2.1@104.933,-18.368 ; 102.599,-19.335 ccw(c102.599,-16.035) P2.1@104.933,-18.368 ; 102.599,-19.335 ccw(c102.599,-16.035) P2.1@104.933,-18.368 ; 102.657,-19.335 cw(c102.657,-22.553) P2.1@104.933,-20.278 ; 102.657,-19.335 cw(c102.657,-22.553) P2.1@104.933,-20.278 ; 102.657,-19.335 cw(c102.657,-22.553) P2.1@104.933,-20.278
  Bottom Layer w1.8: K1.1@97.79,-19.431 ccw(c97.79,-16.365) K1.1@98.551,-19.335 ; K1.1@98.552,-19.335 cw(c98.552,-20.33) 99.255,-19.626 99.432,-19.803 ccw(c101.6,-17.635) 101.6,-20.701 104.521,-20.701 ccw(c104.521,-17.635) P2.1@106.689,-19.803 ; 99.651,-16.891 ccw(c99.651,-18.625) 98.425,-17.399 ccw(c99.958,-18.932) 97.79,-18.932 97.79,-19.177 ccw(c97.79,-17.337) 99.091,-18.638 cw(c100.243,-19.79) 100.243,-18.161 ; 97.028,-21.029 ccw(c97.462,-21.029) 97.155,-21.336 ccw(c98.995,-19.496) 98.995,-22.098 106.163,-22.098 ccw(c106.163,-19.93) 107.696,-21.463 ccw(c107.083,-20.85) 107.95,-20.85 107.95,-17.96 ccw(c107.516,-17.96) 107.823,-17.653 ccw(c105.983,-19.493) 105.983,-16.891 98.806,-16.891 ccw(c98.806,-18.731) 97.505,-17.43 97.409,-17.526 ccw(c98.329,-18.446) 97.028,-18.446 97.028,-21.029
NetP1_2: P1.2 R10.1 | length 13.6
  Bottom Layer w1.5: P1.2 cw(c7.029,-66.458) 8.613,-64.874 ccw(c9.895,-63.593) 9.895,-65.405 17.272,-65.405 ccw(c17.272,-62.339) 19.44,-64.507 19.755,-64.192 cw(c19.892,-64.328) R10.1
NetQ1_1: Q1.1 R2.2 | length 36
  Bottom Layer w1.8: 2.159,-6.477 cw(c4.305,-8.623) 4.305,-5.588 Q1.1 ; R2.2@4.699,-25.741 cw(c4.699,-24.112) 3.547,-25.264 2.667,-24.384 cw(c3.893,-23.158) 2.159,-23.158 2.159,-19.874 cw(c3.534,-19.874) 2.562,-18.901 cw(c3.429,-19.768) 3.429,-18.542 ccw(c3.429,-17.316) 4.296,-18.183 5.842,-16.637 ccw(c5.535,-16.33) 5.969,-16.33 5.969,-7.48 ccw(c2.934,-7.48) Q1.1@5.307,-5.588 ; 3.392,-25.109 ccw(c5.08,-23.42) R2.2@5.08,-25.808 ; 3.392,-25.109 ccw(c5.08,-23.42) R2.2@5.08,-25.808 ; 3.392,-25.109 ccw(c5.08,-23.42) R2.2@5.08,-25.808 ; Q1.1@3.995,-6.292 cw(c5.091,-7.388) Q1.1@5.091,-5.838 ; Q1.1@3.995,-6.292 cw(c5.091,-7.388) Q1.1@5.091,-5.838 ; Q1.1@3.995,-6.292 cw(c5.091,-7.388) Q1.1@5.091,-5.838
NetQ2_1: Q2.1 R6.2 | length 33.1
  Bottom Layer w1.5: R6.2@32.004,-21.971 32.004,-10.414 cw(c35.07,-10.414) 32.902,-8.246 33.646,-7.502 cw(c35.814,-9.67) 35.814,-6.604 49.499,-6.604 cw(c49.499,-7.905) Q2.1@50.419,-6.985
  Bottom Layer w1.8: R6.2 32.004,-20.701
NetQ2_3: Q2.3 Q.2 R7.2 | length 58.3
  Bottom Layer w1: Q.2@39.878,-18.923 Q.2@39.878,-18.796 ; Q.2@39.923,-19.318 cw(c42.944,-18.796) 40.776,-16.628 ; 45.622,-16.51 cw(c45.622,-17.476) R7.2@46.305,-16.793 ; 45.622,-16.51 ccw(c45.622,-15.544) R7.2@46.305,-16.227 ; 45.622,-16.51 cw(c45.622,-17.476) R7.2@46.305,-16.793 ; 45.622,-16.51 ccw(c45.622,-15.544) R7.2@46.305,-16.227 ; 45.622,-16.51 cw(c45.622,-17.476) R7.2@46.305,-16.793 ; 45.622,-16.51 ccw(c45.622,-15.544) R7.2@46.305,-16.227
  Bottom Layer w1.8: 40.776,-16.628 cw(c41.981,-17.833) 41.981,-16.129 55.626,-16.129 ccw(c55.626,-13.063) 57.794,-15.231 59.944,-13.081 ccw(c57.798,-10.935) 60.833,-10.935 Q2.3@60.833,-6.731 ; R7.2@46.736,-16.637 56.642,-16.637 ccw(c56.642,-13.571) 58.81,-15.739 61.205,-13.344 ccw(c59.037,-11.176) 62.103,-11.176 ; 60.833,-7.841 cw(c62.287,-7.841) 61.259,-6.813 cw(c61.457,-7.011) Q2.3 ; 62.103,-11.049 Q2.3@62.103,-6.858
NetQ5_1: Q5.1 Q6.2 | length 6.9
  Bottom Layer w1: Q6.2@91.059,-62.738 91.059,-60.833 cw(c93.818,-60.833) 91.867,-58.882 92.066,-58.683 ccw(c89.898,-56.515) 92.964,-56.515 Q5.1
NetQ_1: Q.1 R5.2 R6.1 | length 83
  Bottom Layer w1: R5.2@14.986,-21.844 cw(c15.599,-22.457) R5.2@15.599,-21.59
  Bottom Layer w1.3: R6.1 23.158,-21.717 cw(c23.158,-23.451) 23.414,-21.736 cw(c23.158,-23.451) 24.384,-22.225 cw(c23.464,-23.145) 24.482,-22.335 cw(c23.464,-23.145) 24.765,-23.145 24.765,-26.289 ccw(c27.831,-26.289) 25.663,-28.457 25.899,-28.693 cw(c23.731,-30.861) 26.797,-30.861 26.797,-49.784 ccw(c29.863,-49.784) 27.695,-51.952 ccw(c29.819,-49.828) 29.376,-52.799 ccw(c29.819,-49.828) 29.819,-52.832 33.274,-52.832 ; 33.401,-52.832 ccw(c33.401,-49.766) 35.569,-51.934 36.322,-51.181 ccw(c34.789,-49.648) 36.957,-49.648 36.957,-30.257 cw(c38.258,-30.257) 37.338,-29.337 ccw(c35.805,-27.804) 37.973,-27.804 Q.1@37.973,-18.542
  Bottom Layer w1.5: R5.2 R6.1
NetR2_1: R2.1 U.1 | length 20.2
  Bottom Layer w1.3: R2.1@15.24,-26.035 16.269,-26.035 ; R2.1 16.129,-25.781 cw(c16.129,-28.847) 18.297,-26.679 18.923,-27.305 cw(c17.39,-28.838) 19.558,-28.838 19.558,-33.677 ccw(c20.425,-33.677) 19.812,-34.29 ccw(c20.732,-33.37) 20.732,-34.671 U.1 ; 18.66,-27.169 18.415,-26.924 ccw(c16.269,-29.07) 16.269,-26.035 ; R2.1@15.507,-25.682 ccw(c16.269,-25.037) 16.269,-26.035 ; R2.1@15.507,-25.682 ccw(c16.269,-25.037) 16.269,-26.035 ; R2.1@15.507,-25.682 ccw(c16.269,-25.037) 16.269,-26.035
OUT: C3.2 K1.3 Q1.3 Q2.2 R3.2 R11.2 | length 201.8
  Bottom Layer w1.3: 16.359,-4.469 17.898,-2.93 cw(c20.066,-5.098) 20.066,-2.032 ; 32.131,-24.511 cw(c33.357,-25.737) 33.357,-24.003 ccw(c33.357,-23.591) 33.649,-23.882 34.535,-22.996 ccw(c32.367,-20.828) 35.433,-20.828
  Bottom Layer w1.5: Q1.3@16.047,-4.781 16.359,-4.469 ; 35.433,-22.851 35.433,-14.478 cw(c38.499,-14.478) 35.434,-14.393 cw(c38.499,-14.478) 36.331,-12.31 36.567,-12.074 cw(c38.735,-14.242) 38.735,-11.176 52.761,-11.176 ccw(c52.761,-9.472) 53.966,-10.677 ccw(c51.798,-8.509) 54.864,-8.509 ; Q1.3@15.991,-5.188 ccw(c15.991,-2.969) 17.56,-4.538 ; Q1.3@15.991,-5.188 ccw(c15.991,-2.969) 17.56,-4.538 ; Q1.3@15.991,-5.188 ccw(c15.991,-2.969) 17.56,-4.538 ; Q1.3@16.391,-5.588 cw(c18.557,-5.588) 17.025,-4.057 ; Q1.3@16.391,-5.588 cw(c19.17,-5.588) 17.205,-3.623 ; Q1.3@16.391,-5.588 cw(c18.557,-5.588) 17.025,-4.057 ; Q1.3@16.391,-5.588 cw(c19.17,-5.588) 17.205,-3.623 ; Q1.3@16.391,-5.588 cw(c18.557,-5.588) 17.025,-4.057 ; Q1.3@16.391,-5.588 cw(c19.17,-5.588) 17.205,-3.623 ; R3.2@32.004,-25.531 ccw(c32.004,-22.475) 34.165,-24.636 ; R3.2@32.004,-25.531 ccw(c32.004,-22.475) 34.165,-24.636 ; R3.2@32.004,-25.531 ccw(c32.004,-22.475) 34.165,-24.636 ; 54.864,-8.845 cw(c56.683,-8.845) Q2.2@56.129,-7.112 ; 54.864,-8.845 cw(c56.683,-8.845) Q2.2@56.129,-7.112 ; 54.864,-8.845 cw(c56.683,-8.845) Q2.2@56.129,-7.112
  Bottom Layer w1.8: 34.671,-24.638 ccw(c33.138,-23.105) 35.306,-23.105 ; 57.776,-3.565 cw(c59.944,-5.733) 59.944,-2.667 88.16,-2.667 cw(c88.16,-3.534) 88.773,-2.921 89.78,-3.928 cw(c87.612,-6.096) 90.678,-6.096 90.678,-26.735 cw(c88.076,-26.735) R11.2@89.963,-28.527 ; K1.3@84.074,-13.589 86.106,-13.589 cw(c86.106,-16.655) 87.611,-13.984 cw(c86.106,-16.655) 88.274,-14.487 89.018,-15.231 cw(c86.85,-17.399) 89.834,-16.695 cw(c86.85,-17.399) 89.916,-17.399 R11.2@89.916,-28.194 ; K1.3 85.09,-13.335 ccw(c85.09,-10.269) 87.258,-12.437 89.018,-10.677 ccw(c86.85,-8.509) 89.916,-8.509 89.916,-5.969 ccw(c86.85,-5.969) 89.018,-3.801 88.782,-3.565 ccw(c86.614,-5.733) 86.614,-2.667 ; 88.147,-13.834 89.907,-12.074 ; 90.043,-26.481 90.043,-5.842 ; R3.2@32.004,-25.681 ccw(c32.004,-22.987) 33.909,-24.892 ; R3.2@32.004,-25.681 ccw(c32.004,-22.987) 33.909,-24.892 ; R3.2@32.004,-25.681 ccw(c32.004,-22.987) 33.909,-24.892 ; R3.2@32.014,-25.681 ccw(c32.22,-23.545) 33.738,-25.063 ; R3.2@32.014,-25.681 ccw(c32.22,-23.545) 33.738,-25.063 ; R3.2@32.014,-25.681 ccw(c32.22,-23.545) 33.738,-25.063
pads on no net: K1.2 P1.3 U.5 U.6 U.7

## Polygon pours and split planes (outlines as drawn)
GND on Bottom Layer (solid): 95.25,-51.689 95.25,-59.69 100.584,-59.69 100.584,-55.035 96.393,-51.834
GND on Bottom Layer (solid): 51.054,-34.29 51.054,-42.592 52.324,-43.862 52.324,-46.007 53.942,-47.625 55.626,-47.625 57.023,-49.022 57.531,-49.53 70.358,-49.53 70.866,-50.038 72.644,-51.816 75.819,-51.816 75.819,-46.609 69.609,-40.399 68.453,-39.243 68.453,-32.004 66.887,-30.438 66.167,-29.718 54.102,-29.718 52.578,-31.242

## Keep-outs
Keep-Out Layer:
  lines w0.4: 0,-71.127 120.015,-71.127 ; 0,-71 0,0 120,0 120,-71

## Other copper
Bottom Layer:
  region net OUT: 31.496,-24.257 31.115,-24.765 30.988,-26.289 31.115,-29.972 32.131,-30.48 33.52,-28.964 35.433,-25.781 35.433,-24.765
  region net NetK1_1: 98.044,-21.844 106.934,-22.352 107.188,-17.399 101.092,-16.891 97.663,-17.272 97.663,-20.193
  region net +12V: 69.692,-23.272 75.819,-15.875 76.454,-16.002 76.454,-22.86 76.835,-25.4 74.549,-25.654
  region net NetQ1_1: 5.461,-4.826 4.953,-5.207 1.651,-6.096 1.27,-6.731 1.27,-14.224 1.27,-21.971 2.794,-20.066 2.794,-21.336 4.826,-18.923 6.096,-16.51 6.477,-13.462
  region net OUT: 17.145,-4.572 21.209,-3.683 51.689,-3.556 53.272,-4.631 53.721,-10.668 54.229,-9.779 54.864,-10.287 56.896,-7.112 57.023,-7.112 59.055,-3.429 59.944,-1.778 20.32,-1.397 17.205,-3.623
  region net -12V: 56.515,-24.297 42.164,-23.495 41.91,-29.337 41.529,-36.703 40.513,-38.862 40.64,-43.307 46.101,-37.592 46.228,-31.115 49.394,-27.441 53.467,-26.543 55.753,-25.908 56.896,-24.638
  region net +12V: 61.849,-25.019 65.405,-25.019 70.612,-30.734 71.755,-35.052 72.644,-37.592 77.343,-42.291 79.375,-42.799 77.343,-38.481 77.343,-36.068 77.343,-24.003 75.946,-23.114 66.294,-23.241 61.087,-23.114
